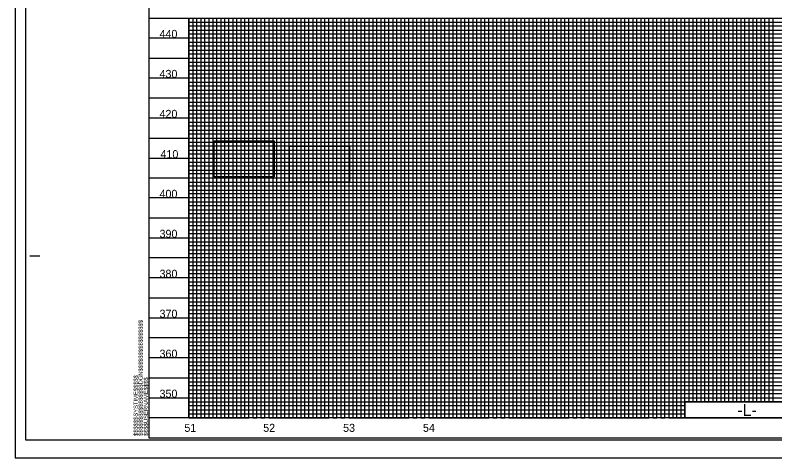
# Model space of a CAD drawing. Extents: x 1632687 to 1634895, y 1174336 to 1175436.
# Drawn here: x 1632687 to 1633637, y 1174336 to 1174889 of the extents above; entities that cross this region are included whole.
import ezdxf

# ---------------------------------------------------------------- set-up
doc = ezdxf.new("R2010")
doc.units = 0
for name, color, linetype in [('Exist Vertical Profile Horizontal Axis Label Major', 7, 'Continuous'), ('Exist Vertical Profile Vertical Axis Label', 7, 'Continuous'), ('Prop Grid Mask', 7, 'Continuous'), ('Sheet Data Field CELL', 7, 'Continuous'), ('Sheet Layout Profile Border Port 2', 7, 'Continuous'), ('Sheet Plan CELL', 7, 'Continuous'), ('Sheet Plot Border Inside CELL', 7, 'Continuous'), ('Sheet Plot Border Outside CELL', 7, 'Continuous'), ('Sheet Profile CELL', 7, 'Continuous'), ('Sheet Profile Grid Major CELL', 7, 'Continuous'), ('Sheet Profile Grid Middle CELL', 7, 'Continuous'), ('Sheet Profile Grid Minor CELL', 7, 'Continuous')]:
    doc.layers.add(name, color=color, linetype=linetype)

msp = doc.modelspace()

# ---------------------------------------------------------------- linework, layer by layer
at = {"layer": 'Prop Grid Mask'}
for points in [[(1632935.98, 1174732.09), (1633010.98, 1174732.09), (1633010.98, 1174687.09), (1632935.98, 1174687.09)], [(1633030.12, 1174725.55), (1633105.12, 1174725.55), (1633105.12, 1174680.55), (1633030.12, 1174680.55)]]:
    msp.add_lwpolyline(points, close=True, dxfattribs=at)
at = {"layer": 'Sheet Data Field CELL'}
msp.add_lwpolyline([(1633524.31, 1174385.79), (1633684.31, 1174385.79), (1633684.31, 1174405.79), (1633524.31, 1174405.79)], close=True, dxfattribs=at)
at = {"layer": 'Sheet Layout Profile Border Port 2'}
msp.add_lwpolyline([(1632904.31, 1174885.79), (1634304.31, 1174885.79), (1634304.31, 1174410.79), (1634104.31, 1174410.79), (1634104.31, 1174385.79), (1633684.31, 1174385.79), (1633684.31, 1174405.79), (1633524.31, 1174405.79), (1633524.31, 1174385.79), (1632904.31, 1174385.79)], close=True, dxfattribs=at)
at = {"layer": 'Sheet Plot Border Inside CELL'}
msp.add_lwpolyline([(1632700.31, 1174358.24), (1634366.81, 1174358.24), (1634366.81, 1175413.34), (1632700.31, 1175413.34)], close=True, dxfattribs=at)
at = {"layer": 'Sheet Plot Border Outside CELL'}
msp.add_lwpolyline([(1632687.31, 1174335.79), (1634371.31, 1174335.79), (1634371.31, 1175435.79), (1632687.31, 1175435.79)], close=True, dxfattribs=at)
at = {"layer": 'Sheet Profile CELL'}
for p, q in [((1632854.31, 1174885.79), (1634354.31, 1174885.79)), ((1632705.81, 1174588.29), (1632718.31, 1174588.29)), ((1634354.31, 1174385.79), (1632854.31, 1174385.79)), ((1632854.31, 1174360.79), (1634354.31, 1174360.79)), ((1632854.31, 1174360.79), (1632854.31, 1174360.79)), ((1632854.31, 1174360.79), (1632854.31, 1174360.79)), ((1632854.31, 1174360.79), (1632854.31, 1174360.79)), ((1632854.31, 1174360.79), (1632854.31, 1174360.79)), ((1632854.31, 1174360.79), (1632854.31, 1174360.79)), ((1632854.31, 1174360.79), (1632854.31, 1174360.79)), ((1632854.31, 1174360.79), (1632854.31, 1174360.79))]:
    msp.add_line(p, q, dxfattribs=at)
msp.add_lwpolyline([(1634354.31, 1175410.79), (1632854.31, 1175410.79), (1632854.31, 1174360.79), (1634354.31, 1174360.79)], close=True, dxfattribs=at)
msp.add_lwpolyline([(1632891.81, 1174360.79), (1632891.81, 1174360.79)], dxfattribs=at)
at = {"layer": 'Sheet Profile Grid Major CELL'}
for p, q in [((1632904.31, 1174885.79), (1632904.31, 1174385.79)), ((1632954.31, 1174385.79), (1632954.31, 1174885.79)), ((1632954.31, 1174885.79), (1633004.31, 1174885.79)), ((1633004.31, 1174885.79), (1633004.31, 1174385.79)), ((1633054.31, 1174385.79), (1633054.31, 1174885.79)), ((1633054.31, 1174885.79), (1633104.31, 1174885.79)), ((1633104.31, 1174885.79), (1633104.31, 1174385.79)), ((1633154.31, 1174385.79), (1633154.31, 1174885.79)), ((1633154.31, 1174885.79), (1633204.31, 1174885.79)), ((1633204.31, 1174885.79), (1633204.31, 1174385.79)), ((1633254.31, 1174385.79), (1633254.31, 1174885.79)), ((1633254.31, 1174885.79), (1633304.31, 1174885.79)), ((1633304.31, 1174885.79), (1633304.31, 1174385.79)), ((1633354.31, 1174885.79), (1633404.31, 1174885.79)), ((1633354.31, 1174385.79), (1633354.31, 1174885.79)), ((1633354.31, 1174885.79), (1633404.31, 1174885.79)), ((1633404.31, 1174885.79), (1633404.31, 1174385.79)), ((1633454.31, 1174885.79), (1633504.31, 1174885.79)), ((1633454.31, 1174385.79), (1633454.31, 1174885.79)), ((1633454.31, 1174885.79), (1633504.31, 1174885.79)), ((1633504.31, 1174885.79), (1633504.31, 1174385.79)), ((1633554.31, 1174885.79), (1633604.31, 1174885.79)), ((1633554.31, 1174405.79), (1633554.31, 1174885.79)), ((1633554.31, 1174885.79), (1633604.31, 1174885.79)), ((1633604.31, 1174885.79), (1633604.31, 1174405.79)), ((1632854.31, 1174385.79), (1632854.31, 1174385.79)), ((1632904.31, 1174385.79), (1632954.31, 1174385.79)), ((1633004.31, 1174385.79), (1633054.31, 1174385.79)), ((1633104.31, 1174385.79), (1633154.31, 1174385.79)), ((1633204.31, 1174385.79), (1633254.31, 1174385.79)), ((1633304.31, 1174385.79), (1633354.31, 1174385.79)), ((1633404.31, 1174385.79), (1633454.31, 1174385.79)), ((1633504.31, 1174385.79), (1633534.31, 1174385.79))]:
    msp.add_line(p, q, dxfattribs=at)
for points in [[(1634354.31, 1174860.79), (1632854.31, 1174860.79)], [(1634354.31, 1174810.79), (1632854.31, 1174810.79)], [(1634354.31, 1174760.79), (1632854.31, 1174760.79), (1632854.31, 1174710.79), (1634354.31, 1174710.79)], [(1634354.31, 1174660.79), (1632854.31, 1174660.79), (1632854.31, 1174610.79), (1634354.31, 1174610.79)], [(1634354.31, 1174560.79), (1632854.31, 1174560.79), (1632854.31, 1174510.79), (1634354.31, 1174510.79)], [(1634354.31, 1174460.79), (1632854.31, 1174460.79), (1632854.31, 1174460.79), (1632854.31, 1174410.79), (1634354.31, 1174410.79)], [(1634354.31, 1174385.79), (1632854.31, 1174385.79)]]:
    msp.add_lwpolyline(points, dxfattribs=at)
at = {"layer": 'Sheet Profile Grid Middle CELL'}
for p, q in [((1633579.31, 1174405.79), (1633579.31, 1174885.79)), ((1633579.31, 1174885.79), (1633629.31, 1174885.79)), ((1633629.31, 1174885.79), (1633629.31, 1174405.79))]:
    msp.add_line(p, q, dxfattribs=at)
for points in [[(1632879.31, 1174885.79), (1632929.31, 1174885.79), (1632929.31, 1174385.79), (1632979.31, 1174385.79), (1632979.31, 1174885.79), (1633029.31, 1174885.79), (1633029.31, 1174385.79), (1633079.31, 1174385.79), (1633079.31, 1174885.79), (1633129.31, 1174885.79), (1633129.31, 1174385.79), (1633179.31, 1174385.79), (1633179.31, 1174885.79), (1633229.31, 1174885.79), (1633229.31, 1174385.79), (1633279.31, 1174385.79), (1633279.31, 1174885.79), (1633329.31, 1174885.79), (1633329.31, 1174385.79), (1633379.31, 1174385.79), (1633379.31, 1174885.79), (1633429.31, 1174885.79), (1633429.31, 1174385.79), (1633479.31, 1174385.79), (1633479.31, 1174385.79), (1633479.31, 1174885.79), (1633529.31, 1174885.79), (1633529.31, 1174405.79)], [(1632854.31, 1174835.79), (1634354.31, 1174835.79)], [(1634354.31, 1174785.79), (1632854.31, 1174785.79), (1632854.31, 1174735.79), (1634354.31, 1174735.79)], [(1634354.31, 1174685.79), (1632854.31, 1174685.79), (1632854.31, 1174635.79), (1634354.31, 1174635.79)], [(1634354.31, 1174585.79), (1632854.31, 1174585.79), (1632854.31, 1174535.79), (1634354.31, 1174535.79)], [(1634354.31, 1174485.79), (1632854.31, 1174485.79), (1632854.31, 1174435.79), (1634354.31, 1174435.79)], [(1634354.31, 1174385.79), (1632854.31, 1174385.79)]]:
    msp.add_lwpolyline(points, dxfattribs=at)
at = {"layer": 'Sheet Profile Grid Minor CELL'}
for p, q in [((1633434.31, 1174885.79), (1633434.31, 1174385.79)), ((1633439.31, 1174385.79), (1633439.31, 1174885.79)), ((1633439.31, 1174885.79), (1633444.31, 1174885.79)), ((1633444.31, 1174885.79), (1633444.31, 1174385.79)), ((1633449.31, 1174385.79), (1633449.31, 1174885.79)), ((1633449.31, 1174885.79), (1633459.31, 1174885.79)), ((1633459.31, 1174885.79), (1633459.31, 1174385.79)), ((1633464.31, 1174385.79), (1633464.31, 1174885.79)), ((1633464.31, 1174885.79), (1633469.31, 1174885.79)), ((1633469.31, 1174885.79), (1633469.31, 1174385.79)), ((1633474.31, 1174385.79), (1633474.31, 1174885.79)), ((1633474.31, 1174885.79), (1633484.31, 1174885.79)), ((1633484.31, 1174885.79), (1633484.31, 1174385.79)), ((1633489.31, 1174385.79), (1633489.31, 1174885.79)), ((1633489.31, 1174885.79), (1633494.31, 1174885.79)), ((1633494.31, 1174885.79), (1633494.31, 1174385.79)), ((1633499.31, 1174385.79), (1633499.31, 1174885.79)), ((1633499.31, 1174885.79), (1633509.31, 1174885.79)), ((1633509.31, 1174885.79), (1633509.31, 1174385.79)), ((1633514.31, 1174385.79), (1633514.31, 1174885.79)), ((1633514.31, 1174885.79), (1633519.31, 1174885.79)), ((1633519.31, 1174885.79), (1633519.31, 1174385.79)), ((1633524.31, 1174385.79), (1633524.31, 1174885.79)), ((1633524.31, 1174885.79), (1633534.31, 1174885.79)), ((1633534.31, 1174885.79), (1633534.31, 1174405.79)), ((1633539.31, 1174405.79), (1633539.31, 1174885.79)), ((1633539.31, 1174885.79), (1633544.31, 1174885.79)), ((1633544.31, 1174885.79), (1633544.31, 1174405.79)), ((1633549.31, 1174405.79), (1633549.31, 1174885.79)), ((1633549.31, 1174885.79), (1633559.31, 1174885.79)), ((1633559.31, 1174885.79), (1633559.31, 1174405.79)), ((1633564.31, 1174405.79), (1633564.31, 1174885.79)), ((1633564.31, 1174885.79), (1633569.31, 1174885.79)), ((1633569.31, 1174885.79), (1633569.31, 1174405.79)), ((1633574.31, 1174405.79), (1633574.31, 1174885.79)), ((1633574.31, 1174885.79), (1633584.31, 1174885.79)), ((1633584.31, 1174885.79), (1633584.31, 1174405.79)), ((1632904.31, 1174880.79), (1634304.31, 1174880.79)), ((1634304.31, 1174875.79), (1632904.31, 1174875.79)), ((1632904.31, 1174870.79), (1634304.31, 1174870.79)), ((1634304.31, 1174865.79), (1632904.31, 1174865.79)), ((1632904.31, 1174855.79), (1634304.31, 1174855.79)), ((1634304.31, 1174850.79), (1632904.31, 1174850.79)), ((1632904.31, 1174845.79), (1634304.31, 1174845.79)), ((1634304.31, 1174840.79), (1632904.31, 1174840.79)), ((1632904.31, 1174830.79), (1634304.31, 1174830.79)), ((1634304.31, 1174825.79), (1632904.31, 1174825.79)), ((1632904.31, 1174820.79), (1634304.31, 1174820.79)), ((1634304.31, 1174815.79), (1632904.31, 1174815.79)), ((1632904.31, 1174805.79), (1634304.31, 1174805.79)), ((1634304.31, 1174800.79), (1632904.31, 1174800.79)), ((1632904.31, 1174795.79), (1634304.31, 1174795.79)), ((1634304.31, 1174790.79), (1632904.31, 1174790.79)), ((1632904.31, 1174780.79), (1634304.31, 1174780.79)), ((1634304.31, 1174775.79), (1632904.31, 1174775.79)), ((1632904.31, 1174770.79), (1634304.31, 1174770.79)), ((1634304.31, 1174765.79), (1632904.31, 1174765.79)), ((1632904.31, 1174755.79), (1634304.31, 1174755.79)), ((1634304.31, 1174750.79), (1632904.31, 1174750.79)), ((1632904.31, 1174745.79), (1634304.31, 1174745.79)), ((1634304.31, 1174740.79), (1632904.31, 1174740.79)), ((1632904.31, 1174730.79), (1634304.31, 1174730.79)), ((1634304.31, 1174725.79), (1632904.31, 1174725.79)), ((1632904.31, 1174720.79), (1634304.31, 1174720.79)), ((1634304.31, 1174715.79), (1632904.31, 1174715.79)), ((1632904.31, 1174705.79), (1634304.31, 1174705.79)), ((1634304.31, 1174700.79), (1632904.31, 1174700.79)), ((1632904.31, 1174695.79), (1634304.31, 1174695.79)), ((1634304.31, 1174690.79), (1632904.31, 1174690.94)), ((1632904.31, 1174680.79), (1634304.31, 1174680.79)), ((1634304.31, 1174675.79), (1632904.31, 1174675.79)), ((1632904.31, 1174670.79), (1634304.31, 1174670.79)), ((1634304.31, 1174665.79), (1632904.31, 1174665.79)), ((1632904.31, 1174655.79), (1634304.31, 1174655.79)), ((1634304.31, 1174650.79), (1632904.31, 1174650.79)), ((1632904.31, 1174645.79), (1634304.31, 1174645.79)), ((1634304.31, 1174640.79), (1632904.31, 1174640.79)), ((1632904.31, 1174630.79), (1634304.31, 1174630.79)), ((1634304.31, 1174625.79), (1632904.31, 1174625.79)), ((1632904.31, 1174620.79), (1634304.31, 1174620.79)), ((1634304.31, 1174615.79), (1632904.31, 1174615.79)), ((1632904.31, 1174605.79), (1634304.31, 1174605.79)), ((1634304.31, 1174600.79), (1632904.31, 1174600.79)), ((1632904.31, 1174595.79), (1634304.31, 1174595.79)), ((1634304.31, 1174590.79), (1632904.31, 1174590.79)), ((1632904.31, 1174580.79), (1634304.31, 1174580.79)), ((1634304.31, 1174575.79), (1632904.31, 1174575.79)), ((1632904.31, 1174570.79), (1634304.31, 1174570.79)), ((1634304.31, 1174565.79), (1632904.31, 1174565.79)), ((1632904.31, 1174555.79), (1634304.31, 1174555.79)), ((1634304.31, 1174550.79), (1632904.31, 1174550.79)), ((1632904.31, 1174545.79), (1634304.31, 1174545.79)), ((1634304.31, 1174540.79), (1632904.31, 1174540.79)), ((1632904.31, 1174530.79), (1634304.31, 1174530.79)), ((1634304.31, 1174525.79), (1632904.31, 1174525.79)), ((1632904.31, 1174520.79), (1634304.31, 1174520.79)), ((1634304.31, 1174515.79), (1632904.31, 1174515.79)), ((1632904.31, 1174505.79), (1634304.31, 1174505.79)), ((1634304.31, 1174500.79), (1632904.31, 1174500.79)), ((1632904.31, 1174495.79), (1634304.31, 1174495.79)), ((1634304.31, 1174490.79), (1632904.31, 1174490.79)), ((1632904.31, 1174480.79), (1634304.31, 1174480.79)), ((1634304.31, 1174475.79), (1632904.31, 1174475.79)), ((1632904.31, 1174470.79), (1634304.31, 1174470.79)), ((1634304.31, 1174465.79), (1632904.31, 1174465.79)), ((1632904.31, 1174455.79), (1634304.31, 1174455.79)), ((1634304.31, 1174450.79), (1632904.31, 1174450.79)), ((1632904.31, 1174445.79), (1634304.31, 1174445.79)), ((1634304.31, 1174440.79), (1632904.31, 1174440.79)), ((1632904.31, 1174430.79), (1634304.31, 1174430.79)), ((1634304.31, 1174425.79), (1632904.31, 1174425.79)), ((1632904.31, 1174420.79), (1634304.31, 1174420.79)), ((1634304.31, 1174415.79), (1632904.31, 1174415.79)), ((1632904.31, 1174405.79), (1634104.31, 1174405.79)), ((1633524.31, 1174400.79), (1632904.31, 1174400.79)), ((1632904.31, 1174395.79), (1633524.31, 1174395.79)), ((1632904.31, 1174390.79), (1633524.31, 1174390.79)), ((1633434.31, 1174385.79), (1633439.31, 1174385.79)), ((1633444.31, 1174385.79), (1633449.31, 1174385.79)), ((1633459.31, 1174385.79), (1633464.31, 1174385.79)), ((1633469.31, 1174385.79), (1633474.31, 1174385.79)), ((1633484.31, 1174385.79), (1633489.31, 1174385.79)), ((1633494.31, 1174385.79), (1633499.31, 1174385.79)), ((1633509.31, 1174385.79), (1633514.31, 1174385.79)), ((1633519.31, 1174385.79), (1633524.31, 1174385.79)), ((1633534.31, 1174385.79), (1633539.31, 1174385.79))]:
    msp.add_line(p, q, dxfattribs=at)
for points in [[(1632904.31, 1174885.79), (1632909.31, 1174885.79), (1632909.31, 1174385.79), (1632914.31, 1174385.79), (1632914.31, 1174885.79), (1632919.31, 1174885.79), (1632919.31, 1174385.79), (1632924.31, 1174385.79), (1632924.31, 1174885.79), (1632934.31, 1174885.79), (1632934.31, 1174385.79), (1632939.31, 1174385.79), (1632939.31, 1174885.79), (1632944.31, 1174885.79), (1632944.31, 1174385.79), (1632949.31, 1174385.79), (1632959.31, 1174385.79), (1632964.31, 1174385.79), (1632964.31, 1174885.79), (1632969.31, 1174885.79), (1632969.31, 1174385.79), (1632974.31, 1174385.79), (1632974.31, 1174885.79), (1632984.31, 1174885.79), (1632984.31, 1174385.79), (1632989.31, 1174385.79), (1632989.31, 1174885.79), (1632994.31, 1174885.79), (1632994.31, 1174385.79), (1632999.31, 1174385.79), (1632999.31, 1174885.79), (1633009.31, 1174885.79), (1633009.31, 1174385.79), (1633014.31, 1174385.79), (1633014.31, 1174885.79), (1633019.31, 1174885.79), (1633019.31, 1174385.79), (1633024.31, 1174385.79), (1633024.31, 1174885.79), (1633034.31, 1174885.79), (1633034.31, 1174385.79), (1633039.31, 1174385.79), (1633039.31, 1174885.79), (1633044.31, 1174885.79), (1633044.31, 1174385.79), (1633049.31, 1174385.79), (1633049.31, 1174885.79), (1633059.31, 1174885.79), (1633059.31, 1174385.79), (1633064.31, 1174385.79), (1633064.31, 1174885.79), (1633069.31, 1174885.79), (1633069.31, 1174385.79), (1633074.31, 1174385.79), (1633074.31, 1174885.79), (1633084.31, 1174885.79), (1633084.31, 1174385.79), (1633089.31, 1174385.79), (1633089.31, 1174885.79), (1633094.31, 1174885.79), (1633094.31, 1174385.79), (1633099.31, 1174385.79), (1633099.31, 1174885.79), (1633109.31, 1174885.79), (1633109.31, 1174385.79), (1633114.31, 1174385.79), (1633114.31, 1174885.79), (1633119.31, 1174885.79), (1633119.31, 1174385.79)], [(1632949.31, 1174385.79), (1632949.31, 1174885.79), (1632959.31, 1174885.79), (1632959.31, 1174385.79)], [(1633119.31, 1174385.79), (1633124.31, 1174385.79), (1633124.31, 1174885.79), (1633134.31, 1174885.79), (1633134.31, 1174385.79), (1633139.31, 1174385.79), (1633139.31, 1174885.79), (1633144.31, 1174885.79), (1633144.31, 1174385.79), (1633149.31, 1174385.79), (1633149.31, 1174885.79), (1633159.31, 1174885.79), (1633159.31, 1174385.79), (1633164.31, 1174385.79), (1633164.31, 1174885.79), (1633169.31, 1174885.79), (1633169.31, 1174385.79), (1633174.31, 1174385.79), (1633174.31, 1174885.79), (1633184.31, 1174885.79), (1633184.31, 1174385.79), (1633189.31, 1174385.79), (1633189.31, 1174885.79), (1633194.31, 1174885.79), (1633194.31, 1174385.79), (1633199.31, 1174385.79), (1633199.31, 1174885.79), (1633209.31, 1174885.79), (1633209.31, 1174385.79), (1633214.31, 1174385.79), (1633214.31, 1174885.79), (1633219.31, 1174885.79), (1633219.31, 1174385.79), (1633224.31, 1174385.79), (1633224.31, 1174885.79), (1633234.31, 1174885.79), (1633234.31, 1174385.79), (1633239.31, 1174385.79), (1633239.31, 1174885.79), (1633244.31, 1174885.79), (1633244.31, 1174385.79), (1633249.31, 1174385.79), (1633249.31, 1174885.79), (1633259.31, 1174885.79), (1633259.31, 1174385.79), (1633264.31, 1174385.79), (1633264.31, 1174885.79), (1633269.31, 1174885.79), (1633269.31, 1174385.79), (1633274.31, 1174385.79), (1633274.31, 1174885.79), (1633284.31, 1174885.79), (1633284.31, 1174385.79), (1633289.31, 1174385.79), (1633289.31, 1174885.79), (1633294.31, 1174885.79), (1633294.31, 1174385.79), (1633299.31, 1174385.79), (1633299.31, 1174885.79), (1633309.31, 1174885.79), (1633309.31, 1174385.79), (1633314.31, 1174385.79), (1633314.31, 1174885.79), (1633319.31, 1174885.79), (1633319.31, 1174385.79), (1633324.31, 1174385.79), (1633324.31, 1174885.79), (1633334.31, 1174885.79), (1633334.31, 1174385.79), (1633339.31, 1174385.79), (1633339.31, 1174885.79), (1633344.31, 1174885.79), (1633344.31, 1174385.79), (1633349.31, 1174385.79), (1633349.31, 1174885.79), (1633359.31, 1174885.79), (1633359.31, 1174385.79), (1633364.31, 1174385.79), (1633364.31, 1174885.79), (1633369.31, 1174885.79), (1633369.31, 1174385.79), (1633374.31, 1174385.79), (1633374.31, 1174885.79), (1633384.31, 1174885.79), (1633384.31, 1174385.79), (1633389.31, 1174385.79), (1633389.31, 1174885.79), (1633394.31, 1174885.79), (1633394.31, 1174385.79), (1633399.31, 1174385.79), (1633399.31, 1174885.79), (1633409.31, 1174885.79), (1633409.31, 1174385.79), (1633414.31, 1174385.79), (1633414.31, 1174885.79), (1633419.31, 1174885.79), (1633419.31, 1174385.79), (1633424.31, 1174385.79), (1633424.31, 1174885.79), (1633434.31, 1174885.79)], [(1633589.31, 1174405.79), (1633589.31, 1174885.79), (1633594.31, 1174885.79), (1633594.31, 1174405.79)], [(1633599.31, 1174405.79), (1633599.31, 1174885.79), (1633609.31, 1174885.79), (1633609.31, 1174405.79)], [(1633614.31, 1174405.79), (1633614.31, 1174885.79), (1633619.31, 1174885.79), (1633619.31, 1174405.79)], [(1633624.31, 1174405.79), (1633624.31, 1174885.79), (1633634.31, 1174885.79), (1633634.31, 1174405.79)]]:
    msp.add_lwpolyline(points, dxfattribs=at)

# ---------------------------------------------------------------- texts
at = {"layer": 'Exist Vertical Profile Horizontal Axis Label Major'}
for s, p in [('51', (1632898.81, 1174368.29)), ('52', (1632997.36, 1174368.29)), ('53', (1633097.2, 1174368.29)), ('54', (1633197.04, 1174368.29))]:
    msp.add_text(s, height=10, dxfattribs=at).set_placement(p)
at = {"layer": 'Exist Vertical Profile Vertical Axis Label'}
for s, p in [('440', (1632867.75, 1174861.04)), ('430', (1632867.75, 1174811.04)), ('420', (1632867.75, 1174761.04)), ('410', (1632868.94, 1174710.69)), ('400', (1632867.75, 1174661.04)), ('390', (1632867.75, 1174611.04)), ('380', (1632867.75, 1174561.04)), ('370', (1632867.75, 1174511.04)), ('360', (1632867.75, 1174461.04)), ('350', (1632867.75, 1174411.04))]:
    msp.add_text(s, height=10, dxfattribs=at).set_placement(p)
at = {"layer": 'Sheet Data Field CELL'}
msp.add_text('-L-', height=15, rotation=360, dxfattribs=at).set_placement((1633589.88, 1174388.29))
at = {"layer": 'Sheet Plan CELL'}
for s, p in [('$$$$$$$$$$$$$$$$DGN$$$$$$$$$$$$$$$$', (1632846.68, 1174363.15)), ('$$$$$$SYSTIME$$$$$', (1632840.6, 1174363.12)), ('$$$$USERNAME$$$$', (1632853.23, 1174363.16))]:
    msp.add_text(s, height=5.25, rotation=90, dxfattribs=at).set_placement(p)

doc.saveas('drawing.dxf')
